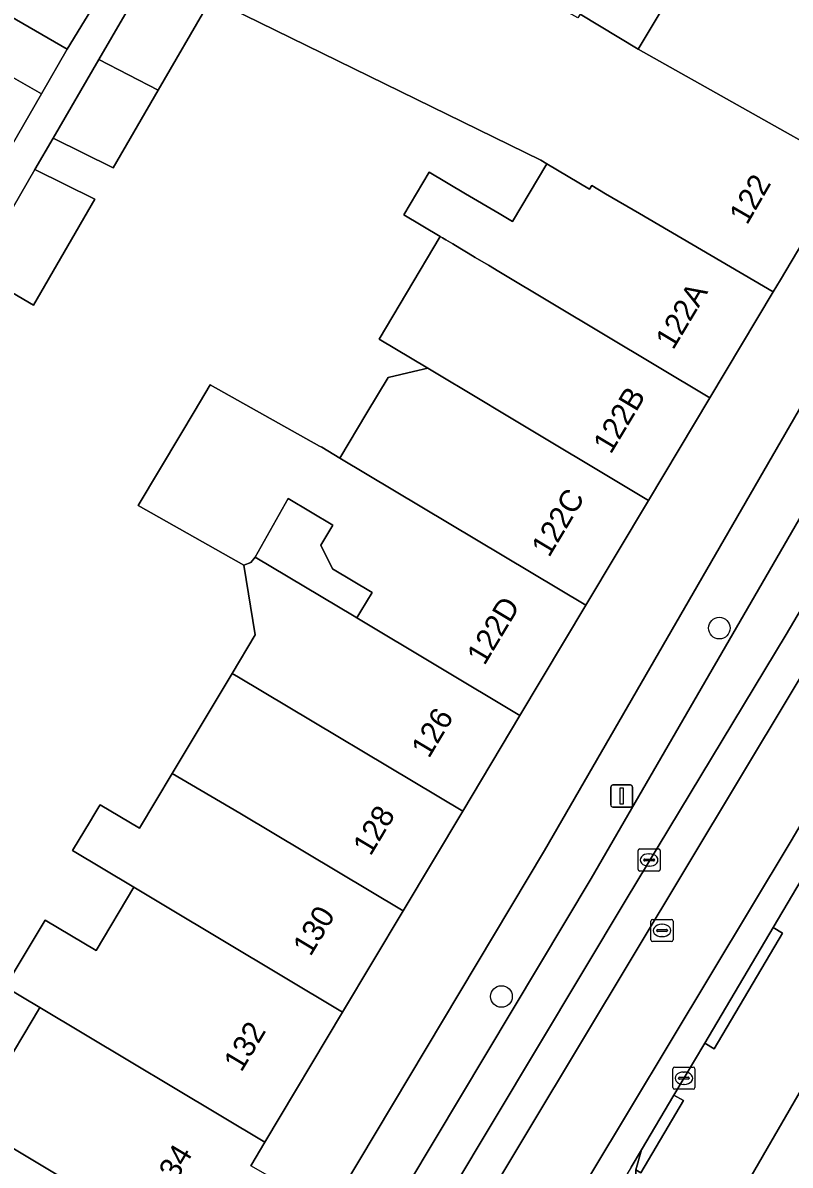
# Model space of a CAD drawing. Extents: x 160349 to 161355, y 381727 to 382854.
# Drawn here: x 160771 to 160805.7, y 382206.9 to 382258.6 of the extents above; entities that cross this region are included whole.
import ezdxf

# ---------------------------------------------------------------- set-up
doc = ezdxf.new("R2010")
doc.units = 0
for name, color, linetype in [('IMGEO_Boom', 7, 'Continuous'), ('IMGEO_Erf', 7, 'Continuous'), ('IMGEO_Kolk', 7, 'Continuous'), ('IMGEO_Lichtmast', 7, 'Continuous'), ('IMGEO_Pand', 7, 'Continuous'), ('IMGEO_Pand_nummerreeks', 7, 'Continuous'), ('IMGEO_Parkeervlak_open', 7, 'Continuous'), ('IMGEO_Rijbaan_lokaal_gesloten', 7, 'Continuous'), ('IMGEO_Rioolput', 7, 'Continuous'), ('IMGEO_Voetpad_open', 7, 'Continuous')]:
    doc.layers.add(name, color=color, linetype=linetype)

msp = doc.modelspace()

# ---------------------------------------------------------------- linework, layer by layer
at = {"layer": 'IMGEO_Boom'}
for centre in [(160802.493, 382231.247), (160792.627, 382214.578)]:
    msp.add_circle(centre, 0.489, dxfattribs=at)
at = {"layer": 'IMGEO_Erf'}
for points in [[(160772.407, 382184.113), (160794.573, 382221.181), (160811.234, 382250), (160815.558, 382257.479), (160828.746, 382282.08)], [(160796.186, 382259.019), (160798.82, 382257.443), (160803.356, 382265.025)], [(160770.149, 382211.44), (160771.376, 382213.49), (160771.622, 382213.901), (160771.727, 382214.075), (160770.155, 382215.014), (160771.959, 382218.034), (160774.272, 382216.652), (160775.984, 382219.52), (160773.209, 382221.177), (160774.016, 382222.525), (160774.172, 382222.785), (160774.263, 382222.938), (160774.393, 382223.155), (160774.451, 382223.252), (160776.245, 382222.196), (160777.724, 382224.668), (160780.433, 382229.197), (160781.477, 382230.941), (160780.962, 382234.089), (160776.175, 382236.79), (160778.105, 382240.017), (160778.709, 382241.027), (160779.444, 382242.256), (160784.386, 382239.485), (160784.496, 382239.431), (160785.313, 382238.942), (160786.535, 382240.986), (160787.496, 382242.591), (160788.65, 382242.857), (160789.288, 382243.004), (160787.091, 382244.319), (160788.333, 382246.408), (160789.853, 382248.964), (160788.207, 382249.949), (160789.36, 382251.877), (160791.004, 382250.9), (160792.519, 382250), (160793.124, 382249.641), (160794.68, 382252.259), (160794.418, 382252.416), (160777.45, 382260.733)], [(160769.791, 382259.267), (160772.959, 382257.437), (160774.526, 382260.018)], [(160812.852, 382260.124), (160808.268, 382252.126), (160807.561, 382250.892), (160807.05, 382250), (160805.262, 382247.012), (160804.93, 382246.459), (160802.064, 382241.667), (160799.285, 382237.023), (160796.448, 382232.281), (160793.463, 382227.292), (160790.872, 382222.961), (160788.171, 382218.448), (160785.436, 382213.876), (160781.915, 382207.991), (160781.273, 382206.918)], [(160779.362, 382259.504), (160777.086, 382255.586), (160775.049, 382252.078), (160772.329, 382253.419), (160771.5, 382251.991), (160774.219, 382250.65), (160771.439, 382245.863), (160768.823, 382247.382)], [(160933.344, 382182.327), (160924.218, 382191.389), (160906.426, 382206.128), (160902.418, 382205.455), (160886.177, 382214.66), (160875.171, 382221.124), (160873.887, 382226.28), (160832.686, 382250), (160830.042, 382251.522), (160829.161, 382250), (160786.376, 382176.128), (160847.679, 382140.543), (160850.05, 382144.635)], [(160774.494, 382205.327), (160771.787, 382206.947), (160768.599, 382208.851)]]:
    msp.add_lwpolyline(points, dxfattribs=at)
msp.add_lwpolyline([(160781.48, 382234.462), (160785.957, 382231.783), (160786.077, 382231.711), (160786.258, 382232.013), (160786.766, 382232.863), (160784.982, 382233.928), (160784.449, 382234.992), (160784.995, 382235.904), (160782.969, 382237.116)], close=True, dxfattribs=at)
at = {"layer": 'IMGEO_Kolk'}
for p, q in [((160798.814, 382220.328), (160798.814, 382221.18)), ((160798.889, 382221.254), (160799.741, 382221.254)), ((160799.302, 382221.034), (160799.327, 382221.034)), ((160799.815, 382221.18), (160799.815, 382220.328)), ((160799.073, 382220.748), (160799.073, 382220.76)), ((160799.511, 382220.711), (160799.113, 382220.711)), ((160799.116, 382220.797), (160799.514, 382220.797)), ((160799.325, 382220.474), (160799.3, 382220.474)), ((160799.557, 382220.76), (160799.557, 382220.748)), ((160799.741, 382220.254), (160798.889, 382220.254)), ((160800.389, 382210.454), (160800.389, 382211.306)), ((160800.464, 382211.38), (160801.316, 382211.38)), ((160800.877, 382211.16), (160800.902, 382211.16)), ((160801.39, 382211.306), (160801.39, 382210.454)), ((160800.648, 382210.874), (160800.648, 382210.886)), ((160801.086, 382210.837), (160800.688, 382210.837)), ((160800.691, 382210.923), (160801.089, 382210.923)), ((160800.9, 382210.6), (160800.875, 382210.6)), ((160801.132, 382210.886), (160801.132, 382210.874)), ((160801.316, 382210.38), (160800.464, 382210.38))]:
    msp.add_line(p, q, dxfattribs=at)
for points in [[(160798.814, 382220.328), (160798.814, 382221.18)], [(160798.889, 382221.254), (160799.741, 382221.254)], [(160799.815, 382221.18), (160799.815, 382220.328)], [(160799.741, 382220.254), (160798.889, 382220.254)], [(160800.389, 382210.454), (160800.389, 382211.306)], [(160800.464, 382211.38), (160801.316, 382211.38)], [(160801.39, 382211.306), (160801.39, 382210.454)], [(160801.316, 382210.38), (160800.464, 382210.38)]]:
    msp.add_lwpolyline(points, dxfattribs=at)
for centre, radius, start, end in [((160798.891, 382221.178), 0.0765, 91.552, 178.448), ((160798.891, 382221.178), 0.0765, 91.552, 178.448), ((160799.739, 382221.178), 0.0765, 1.552, 88.448), ((160799.739, 382221.178), 0.0765, 1.552, 88.448), ((160799.113, 382220.757), 0.0403, 85.8775, 175.7526), ((160799.11, 382220.747), 0.0366, 178.938, 274.7102), ((160799.514, 382220.754), 0.043, 264.8664, 352.4533), ((160799.518, 382220.759), 0.0386, 1.7309, 96.639), ((160798.891, 382220.33), 0.0765, 181.552, 268.448), ((160798.891, 382220.33), 0.0765, 181.552, 268.448), ((160799.739, 382220.33), 0.0765, 271.552, 358.448), ((160799.739, 382220.33), 0.0765, 271.552, 358.448), ((160800.466, 382211.304), 0.0765, 91.552, 178.448), ((160800.466, 382211.304), 0.0765, 91.552, 178.448), ((160801.314, 382211.304), 0.0765, 1.552, 88.448), ((160801.314, 382211.304), 0.0765, 1.552, 88.448), ((160800.688, 382210.883), 0.0403, 85.8775, 175.7526), ((160800.685, 382210.873), 0.0366, 178.938, 274.7102), ((160801.089, 382210.88), 0.043, 264.8664, 352.4533), ((160801.093, 382210.885), 0.0386, 1.7309, 96.639), ((160800.466, 382210.456), 0.0765, 181.552, 268.448), ((160800.466, 382210.456), 0.0765, 181.552, 268.448), ((160801.314, 382210.456), 0.0765, 271.552, 358.448), ((160801.314, 382210.456), 0.0765, 271.552, 358.448)]:
    msp.add_arc(centre, radius, start, end, dxfattribs=at)
for centre, major_axis, ratio, start_param, end_param in [((160799.301, 382220.754), (-0.387, 0.002), 0.722429, 4.712389, 7.853982), ((160799.326, 382220.754), (-0.39, 0.002), 0.717154, 1.570796, 4.712389), ((160800.876, 382210.88), (-0.387, 0.002), 0.722429, 4.712389, 7.853982), ((160800.901, 382210.88), (-0.39, 0.002), 0.717154, 1.570796, 4.712389)]:
    msp.add_ellipse(centre, major_axis=major_axis, ratio=ratio, start_param=start_param, end_param=end_param, dxfattribs=at)
at = {"layer": 'IMGEO_Lichtmast'}
for p, q in [((160797.576, 382223.248), (160797.576, 382224.048)), ((160797.576, 382224.048), (160797.576, 382223.248)), ((160797.676, 382224.148), (160798.466, 382224.148)), ((160798.466, 382224.148), (160797.676, 382224.148)), ((160798.566, 382224.048), (160798.566, 382223.248)), ((160798.566, 382223.248), (160798.566, 382224.048)), ((160798.466, 382223.148), (160797.676, 382223.148)), ((160797.676, 382223.148), (160798.466, 382223.148))]:
    msp.add_line(p, q, dxfattribs=at)
msp.add_lwpolyline([(160797.996, 382224.023), (160798.146, 382224.023), (160798.146, 382223.273), (160797.996, 382223.273), (160797.996, 382224.023)], dxfattribs=at)
for centre, start, end in [((160797.676, 382224.048), 90, 180), ((160797.676, 382224.048), 90, 180), ((160798.466, 382224.048), 0, 90), ((160798.466, 382224.048), 360, 90), ((160797.676, 382223.248), 180, 270), ((160797.676, 382223.248), 180, 270), ((160798.466, 382223.248), 270, 0), ((160798.466, 382223.248), 270, 0)]:
    msp.add_arc(centre, 0.1, start, end, dxfattribs=at)
at = {"layer": 'IMGEO_Pand'}
for points in [[(160798.82, 382257.443), (160796.186, 382259.019), (160796.093, 382258.863), (160791.968, 382261.147), (160791.47, 382260.265), (160786.388, 382263.114), (160787.765, 382265.504), (160782.2, 382268.389), (160777.45, 382260.733), (160794.418, 382252.416), (160794.68, 382252.259), (160796.617, 382251.1), (160796.718, 382251.27), (160797.346, 382250.895), (160798.876, 382250), (160804.93, 382246.459), (160805.262, 382247.012), (160807.05, 382250), (160807.561, 382250.892), (160808.268, 382252.126)], [(160808.268, 382252.126), (160812.852, 382260.124), (160804.476, 382264.541), (160803.356, 382265.025), (160798.82, 382257.443)], [(160779.362, 382259.504), (160777.399, 382260.645), (160776.746, 382261.024), (160774.398, 382256.981), (160777.086, 382255.586)], [(160768.61, 382257.223), (160771.796, 382255.423), (160772.959, 382257.437), (160769.791, 382259.267)], [(160771.796, 382255.423), (160768.61, 382257.223), (160767.524, 382255.342), (160767.076, 382255.595), (160766.293, 382255.463), (160764.688, 382252.685), (160764.812, 382251.908), (160765.359, 382251.592), (160768.527, 382249.762)], [(160777.086, 382255.586), (160774.398, 382256.981), (160772.329, 382253.419), (160775.049, 382252.078)], [(160771.5, 382251.991), (160768.823, 382247.382), (160771.439, 382245.863), (160774.219, 382250.65)], [(160798.876, 382250), (160797.346, 382250.895), (160796.718, 382251.27), (160796.617, 382251.1), (160794.68, 382252.259), (160793.124, 382249.641), (160792.519, 382250), (160791.004, 382250.9), (160789.36, 382251.877), (160788.207, 382249.949), (160789.853, 382248.964), (160789.955, 382248.911), (160790.114, 382248.816), (160790.428, 382248.628), (160790.74, 382248.441), (160791.128, 382248.209), (160791.445, 382248.02), (160792.035, 382247.666), (160792.51, 382247.383), (160802.064, 382241.667), (160804.93, 382246.459)], [(160789.853, 382248.964), (160788.333, 382246.408), (160787.091, 382244.319), (160789.288, 382243.004), (160791.811, 382241.495), (160792.458, 382241.108), (160799.285, 382237.023), (160802.064, 382241.667), (160792.51, 382247.383), (160792.035, 382247.666), (160791.445, 382248.02), (160791.128, 382248.209), (160790.74, 382248.441), (160790.428, 382248.628), (160790.114, 382248.816), (160789.955, 382248.911)], [(160789.288, 382243.004), (160788.65, 382242.857), (160787.496, 382242.591), (160786.535, 382240.986), (160785.313, 382238.942), (160796.448, 382232.281), (160799.285, 382237.023), (160792.458, 382241.108), (160791.811, 382241.495)], [(160785.313, 382238.942), (160784.496, 382239.431), (160784.386, 382239.485), (160779.444, 382242.256), (160778.709, 382241.027), (160778.105, 382240.017), (160776.175, 382236.79), (160780.962, 382234.089), (160781.28, 382234.213), (160781.48, 382234.462), (160782.969, 382237.116), (160784.995, 382235.904), (160784.449, 382234.992), (160784.982, 382233.928), (160786.766, 382232.863), (160786.258, 382232.013), (160786.077, 382231.711), (160793.463, 382227.292), (160796.448, 382232.281)], [(160786.077, 382231.711), (160785.957, 382231.783), (160781.48, 382234.462), (160781.28, 382234.213), (160780.962, 382234.089), (160781.477, 382230.941), (160780.433, 382229.197), (160780.725, 382229.032), (160790.872, 382222.961), (160793.463, 382227.292)], [(160780.433, 382229.197), (160777.724, 382224.668), (160780.785, 382222.867), (160788.171, 382218.448), (160790.872, 382222.961), (160780.725, 382229.032)], [(160780.785, 382222.867), (160777.724, 382224.668), (160776.245, 382222.196), (160774.451, 382223.252), (160774.393, 382223.155), (160774.263, 382222.938), (160774.172, 382222.785), (160774.016, 382222.525), (160773.209, 382221.177), (160775.984, 382219.52), (160777.344, 382218.708), (160785.436, 382213.876), (160788.171, 382218.448)], [(160777.344, 382218.708), (160775.984, 382219.52), (160774.272, 382216.652), (160771.959, 382218.034), (160770.155, 382215.014), (160771.727, 382214.075), (160781.915, 382207.991), (160785.436, 382213.876)], [(160771.727, 382214.075), (160771.622, 382213.901), (160771.376, 382213.49), (160770.149, 382211.44), (160768.554, 382212.392), (160767.004, 382209.803), (160768.599, 382208.851), (160771.787, 382206.947), (160774.494, 382205.327), (160778.785, 382202.76), (160779.466, 382203.898), (160780.279, 382203.438), (160781.107, 382203.64), (160782.296, 382205.652), (160782.047, 382206.482), (160781.273, 382206.918), (160781.915, 382207.991)]]:
    msp.add_lwpolyline(points, close=True, dxfattribs=at)
at = {"layer": 'IMGEO_Parkeervlak_open'}
for points in [[(160781.786, 382191.466), (160786.323, 382199.028), (160798.28, 382218.963), (160805.521, 382230.961), (160817.325, 382250.962), (160826.186, 382266.882), (160838.167, 382290.047), (160842.376, 382298.812)], [(160839.013, 382296.685), (160829.617, 382277.989), (160823.877, 382267.074), (160820.834, 382261.421), (160816.429, 382253.709), (160815.075, 382251.417), (160814.238, 382250), (160812.776, 382247.525), (160807.918, 382239.299), (160796.693, 382219.912), (160784.85, 382200.156), (160781.859, 382195.236), (160781.646, 382194.422), (160781.963, 382193.031)], [(160799.013, 382204.786), (160798.729, 382206.085), (160798.713, 382206.735), (160798.962, 382207.633), (160798.503, 382206.859), (160795.414, 382201.651), (160791.017, 382194.317), (160787.293, 382188.166)]]:
    msp.add_lwpolyline(points, dxfattribs=at)
at = {"layer": 'IMGEO_Rijbaan_lokaal_gesloten'}
for points in [[(160870.039, 382363.675), (160863.441, 382345.553), (160862.813, 382344.017), (160858.578, 382333.835), (160856.293, 382328.731), (160854.763, 382325.314), (160854.74, 382325.262), (160850.03, 382314.742), (160844.333, 382302.883), (160842.376, 382298.812), (160838.167, 382290.047), (160826.186, 382266.882), (160817.325, 382250.962), (160805.521, 382230.961), (160798.28, 382218.963), (160786.323, 382199.028)], [(160798.503, 382206.859), (160798.962, 382207.633), (160800.434, 382210.12), (160801.83, 382212.468), (160804.931, 382217.699), (160806.44, 382220.243), (160820.447, 382243.859), (160823.843, 382250), (160824.345, 382250.697), (160824.515, 382250.932), (160833.193, 382266.844), (160846.051, 382292.081), (160846.152, 382292.278), (160846.237, 382292.445), (160848.99, 382298.282), (160849.068, 382298.447), (160856.008, 382313.16), (160856.147, 382313.455), (160858.959, 382319.416), (160859.359, 382320.315), (160867.708, 382339.101), (160867.955, 382339.717), (160869.629, 382343.884), (160875.162, 382358.523)], [(160792.985, 382200.423), (160805.748, 382221.628), (160816.567, 382239.989), (160824.699, 382254.022), (160830.666, 382264.645), (160835.649, 382274.12), (160839.879, 382282.612), (160846.567, 382296.087), (160853.059, 382309.759), (160859.092, 382322.809), (160864.338, 382334.874), (160869.059, 382345.759), (160870.928, 382350.579), (160873.42, 382357.694)], [(160873.42, 382357.694), (160870.928, 382350.579), (160869.059, 382345.759), (160864.338, 382334.874), (160859.092, 382322.809), (160853.059, 382309.759), (160846.567, 382296.087), (160839.879, 382282.612), (160835.649, 382274.12), (160830.666, 382264.645), (160824.699, 382254.022), (160816.567, 382239.989), (160805.748, 382221.628), (160792.985, 382200.423)], [(160784.239, 382192.537), (160812.989, 382240.37), (160826.989, 382265.037), (160837.239, 382284.953), (160845.281, 382301.287), (160850.947, 382313.328), (160862.656, 382339.12), (160868.864, 382355.162)], [(160868.864, 382355.162), (160862.656, 382339.12), (160850.947, 382313.328), (160845.281, 382301.287), (160837.239, 382284.953), (160826.989, 382265.037), (160812.989, 382240.37), (160784.239, 382192.537)]]:
    msp.add_lwpolyline(points, dxfattribs=at)
at = {"layer": 'IMGEO_Rioolput'}
for p, q in [((160799.398, 382217.14), (160799.398, 382217.992)), ((160799.473, 382218.066), (160800.325, 382218.066)), ((160799.886, 382217.846), (160799.911, 382217.846)), ((160800.399, 382217.992), (160800.399, 382217.14)), ((160799.657, 382217.56), (160799.657, 382217.572)), ((160800.095, 382217.523), (160799.697, 382217.523)), ((160799.7, 382217.609), (160800.098, 382217.609)), ((160799.909, 382217.286), (160799.884, 382217.286)), ((160800.141, 382217.572), (160800.141, 382217.56)), ((160800.325, 382217.066), (160799.473, 382217.066))]:
    msp.add_line(p, q, dxfattribs=at)
for points in [[(160799.398, 382217.14), (160799.398, 382217.992)], [(160799.473, 382218.066), (160800.325, 382218.066)], [(160800.399, 382217.992), (160800.399, 382217.14)], [(160800.325, 382217.066), (160799.473, 382217.066)]]:
    msp.add_lwpolyline(points, dxfattribs=at)
for centre, radius, start, end in [((160799.475, 382217.99), 0.0765, 91.552, 178.448), ((160799.475, 382217.99), 0.0765, 91.552, 178.448), ((160800.323, 382217.99), 0.0765, 1.552, 88.448), ((160800.323, 382217.99), 0.0765, 1.552, 88.448), ((160799.697, 382217.569), 0.0403, 85.8775, 175.7526), ((160799.694, 382217.559), 0.0366, 178.938, 274.7102), ((160800.098, 382217.566), 0.043, 264.8664, 352.4533), ((160800.102, 382217.571), 0.0386, 1.7309, 96.639), ((160799.475, 382217.142), 0.0765, 181.552, 268.448), ((160799.475, 382217.142), 0.0765, 181.552, 268.448), ((160800.323, 382217.142), 0.0765, 271.552, 358.448), ((160800.323, 382217.142), 0.0765, 271.552, 358.448)]:
    msp.add_arc(centre, radius, start, end, dxfattribs=at)
for centre, major_axis, ratio, start_param, end_param in [((160799.885, 382217.566), (-0.387, 0.002), 0.722429, 4.712389, 7.853982), ((160799.91, 382217.566), (-0.39, 0.002), 0.717154, 1.570796, 4.712389)]:
    msp.add_ellipse(centre, major_axis=major_axis, ratio=ratio, start_param=start_param, end_param=end_param, dxfattribs=at)
at = {"layer": 'IMGEO_Voetpad_open'}
for points in [[(160843.818, 382306.679), (160846.821, 382312.974), (160844.409, 382314.087), (160840.283, 382305.069), (160838.339, 382300.821), (160828.746, 382282.08), (160815.558, 382257.479), (160811.234, 382250), (160794.573, 382221.181), (160772.407, 382184.113), (160770.967, 382181.708)], [(160781.963, 382193.031), (160781.646, 382194.422), (160781.859, 382195.236), (160784.85, 382200.156), (160796.693, 382219.912), (160807.918, 382239.299), (160812.776, 382247.525), (160812.345, 382247.775), (160813.659, 382250), (160814.643, 382251.667), (160815.075, 382251.417), (160816.429, 382253.709), (160820.834, 382261.421), (160823.877, 382267.074), (160829.617, 382277.989), (160839.013, 382296.685)], [(160768.823, 382247.382), (160771.5, 382251.991), (160772.329, 382253.419), (160774.398, 382256.981), (160776.746, 382261.024), (160777.399, 382260.645), (160777.45, 382260.733), (160782.2, 382268.389), (160783.657, 382270.738), (160781.657, 382271.776), (160780.768, 382270.309), (160779.269, 382267.836), (160778.029, 382265.789), (160776.819, 382263.796), (160774.526, 382260.018), (160772.959, 382257.437), (160771.796, 382255.423), (160768.527, 382249.762)], [(160785.65, 382171.897), (160786.376, 382176.128), (160829.161, 382250)], [(160824.181, 382246.765), (160816.635, 382233.947), (160808.563, 382220.384), (160808.01, 382219.333), (160806.44, 382220.243), (160804.931, 382217.699), (160805.361, 382217.445), (160802.26, 382212.214), (160801.83, 382212.468), (160800.434, 382210.12), (160800.864, 382209.866), (160798.933, 382206.605), (160798.713, 382206.735), (160798.729, 382206.085), (160799.013, 382204.786)]]:
    msp.add_lwpolyline(points, dxfattribs=at)
for points in [[(160801.83, 382212.468), (160802.26, 382212.214), (160805.361, 382217.445), (160804.931, 382217.699)], [(160798.713, 382206.735), (160798.933, 382206.605), (160800.864, 382209.866), (160800.434, 382210.12), (160798.962, 382207.633)]]:
    msp.add_lwpolyline(points, close=True, dxfattribs=at)

# ---------------------------------------------------------------- texts
at = {"layer": 'IMGEO_Pand_nummerreeks'}
for s, rotation, p in [('122', 59.96, (160803.75, 382249.452)), ('122A', 59.1178, (160800.402, 382243.796)), ('122B', 59.1063, (160797.579, 382239.079)), ('122C', 59.1063, (160794.784, 382234.408)), ('122D', 59.1063, (160791.86, 382229.52)), ('126', 59.1063, (160789.343, 382225.316)), ('128', 59.1067, (160786.7, 382220.897)), ('130', 59.1063, (160783.981, 382216.354)), ('132', 59.1063, (160780.85, 382211.12)), ('134', 59.1063, (160777.525, 382205.565))]:
    msp.add_text(s, height=1, rotation=rotation, dxfattribs=at).set_placement(p)

doc.saveas('drawing.dxf')
